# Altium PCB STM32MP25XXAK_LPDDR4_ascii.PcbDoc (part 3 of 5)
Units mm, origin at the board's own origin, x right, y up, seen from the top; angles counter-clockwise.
Board outline 120 x 79.6 mm, 4 copper layers (Top Layer, Signal Layer 1, Signal Layer 2, Bottom Layer), stack 1.614 mm thick; 190 components, 143 nets, 1208 pads, 757 vias.
Unrouted connection lines stored in the file: 3.
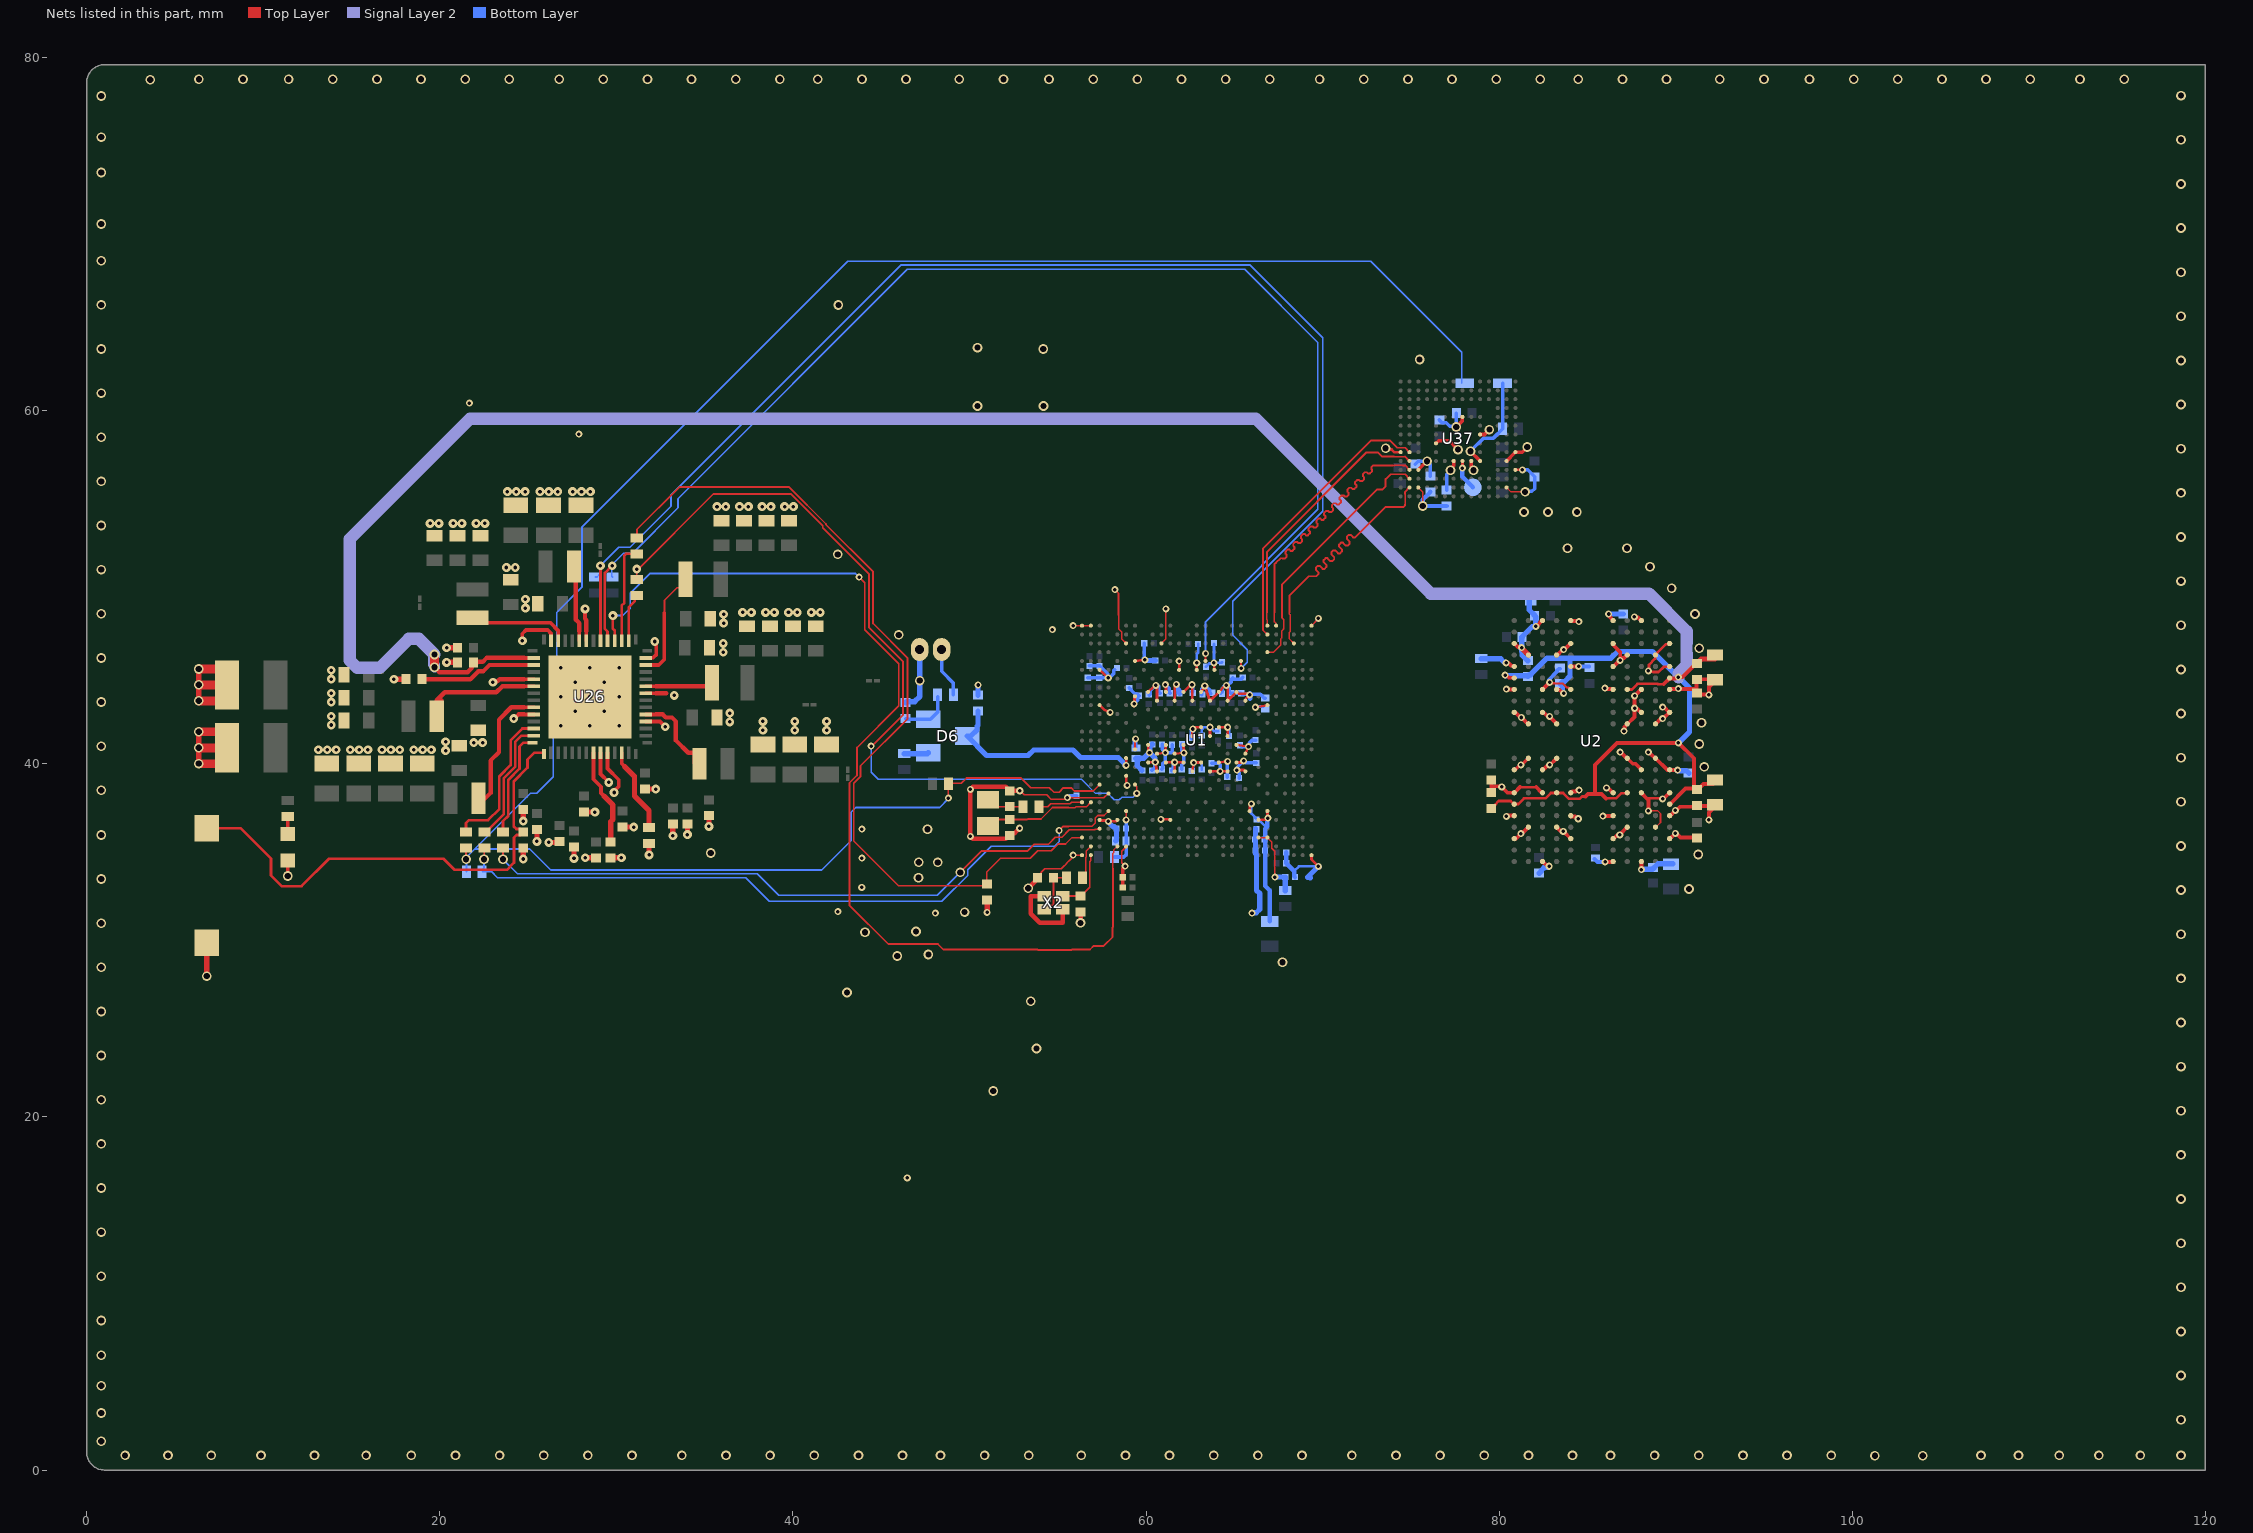
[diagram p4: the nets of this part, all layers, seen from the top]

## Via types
v1: diameter 0.55, hole 0.35, Top Layer to Bottom Layer, 277 vias
v2: diameter 0.4, hole 0.2, Top Layer to Bottom Layer, tented both sides, 229 vias
v3: diameter 0.5, hole 0.2, Top Layer to Bottom Layer, 146 vias
v4: diameter 0.4, hole 0.2, Top Layer to Bottom Layer, 105 vias

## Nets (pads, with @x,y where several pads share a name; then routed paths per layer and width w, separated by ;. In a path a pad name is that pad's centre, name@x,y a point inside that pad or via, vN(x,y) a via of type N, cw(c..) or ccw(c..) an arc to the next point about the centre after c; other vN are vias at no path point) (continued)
eMMC.SDMMC2_D3: U1.C25 U37.B2 | length 15.5
  Top Layer w0.09: 68.125,48.575 68.125,48.489 68.165,48.449 68.165,47.498 68.125,47.458 68.125,47.075 U1.C25@68.375,46.825 ; 74.675,54.705 74.675,55.273
  Top Layer w0.11: 68.125,48.575 68.125,49.525 69.225,50.625 69.647,50.625 69.723,50.702 69.762,50.741 69.762,50.85 69.621,50.991 69.621,51.101 69.731,51.211 69.84,51.211 70.004,51.046 70.114,51.046 70.224,51.156 70.224,51.266 70.059,51.43 70.059,51.539 70.169,51.649 70.279,51.649 70.443,51.485 70.552,51.485 70.662,51.594 70.662,51.704 70.498,51.868 70.498,51.978 70.607,52.087 70.717,52.087 70.881,51.923 70.991,51.923 71.1,52.033 71.1,52.142 70.936,52.307 70.936,52.416 71.046,52.526 71.155,52.526 71.32,52.362 71.429,52.362 71.539,52.471 71.539,52.581 71.375,52.745 71.375,52.855 71.484,52.964 71.594,52.964 71.735,52.823 71.845,52.823 71.887,52.865 73.582,54.56 74.596,54.56 74.675,54.639 74.675,54.705 ; 74.675,55.273 74.675,55.405 U37.B2@74.925,55.655
eMMC.SDMMC2_D4: U1.D22 U37.B3 | length 14.7
  Top Layer w0.09: U1.D22@66.902,46.352 U1.D22@66.875,46.325 67.229,46.325 67.625,46.721 67.625,47.075 67.7,47.15 67.7,47.541 67.805,47.647 67.805,48.17 67.7,48.275 ; 74.056,56.405 74.543,56.405
  Top Layer w0.11: 67.7,48.275 67.692,48.283 67.692,50.142 73.1,55.55 73.4,55.55 73.575,55.725 73.575,56.125 73.855,56.405 74.056,56.405 ; 74.543,56.405 74.675,56.405 U37.B3@74.925,56.155
eMMC.SDMMC2_D5: U1.A23 U37.B4 | length 17.3
  Top Layer w0.09: 67.267,48.575 67.267,48.055 67.349,47.973 67.349,47.851 U1.A23@67.375,47.825 ; 74.056,56.905 74.543,56.905
  Top Layer w0.11: 67.267,48.575 67.267,51.292 67.362,51.387 67.621,51.646 67.73,51.646 67.75,51.625 67.86,51.625 67.97,51.735 67.97,51.845 67.901,51.913 67.901,52.022 68.011,52.132 68.121,52.132 68.189,52.064 68.298,52.064 68.408,52.173 68.408,52.283 68.34,52.351 68.34,52.461 68.449,52.57 68.559,52.57 68.627,52.502 68.737,52.502 68.846,52.612 68.846,52.721 68.778,52.79 68.778,52.899 68.888,53.009 68.997,53.009 69.066,52.941 69.175,52.941 69.285,53.05 69.285,53.16 69.217,53.228 69.217,53.338 69.326,53.447 69.436,53.447 69.504,53.379 69.614,53.379 69.723,53.489 69.723,53.598 69.655,53.666 69.655,53.776 69.765,53.886 69.874,53.886 69.942,53.817 70.052,53.817 70.162,53.927 70.162,54.037 70.093,54.105 70.093,54.214 70.203,54.324 70.313,54.324 70.381,54.256 70.49,54.256 70.6,54.365 70.6,54.475 70.532,54.543 70.532,54.653 70.641,54.762 70.751,54.762 70.819,54.694 70.929,54.694 71.038,54.804 71.038,54.913 70.97,54.982 70.97,55.091 71.08,55.201 71.189,55.201 71.258,55.133 71.367,55.133 71.477,55.242 71.477,55.352 71.409,55.42 71.409,55.53 71.518,55.639 71.628,55.639 71.696,55.571 71.806,55.571 71.915,55.681 71.915,55.79 71.847,55.858 71.847,55.968 71.957,56.078 72.066,56.078 72.134,56.01 72.244,56.01 72.354,56.119 72.354,56.229 72.285,56.297 72.285,56.406 72.395,56.516 72.505,56.516 72.573,56.448 72.682,56.448 72.792,56.558 72.792,56.667 72.772,56.687 72.772,56.797 72.88,56.905 72.912,56.905 74.056,56.905 ; 74.543,56.905 74.675,56.905 U37.B4@74.925,56.655
eMMC.SDMMC2_D6: U1.A22 U37.B5 | length 14.8
  Top Layer w0.09: 66.847,48.356 66.847,48.176 66.875,48.148 U1.A22@66.875,47.825 ; 74.056,57.405 74.675,57.405
  Top Layer w0.096: 66.847,48.356 66.847,48.575
  Top Layer w0.11: 66.847,48.575 66.847,51.997 72.49,57.64 73.14,57.64 73.375,57.405 74.056,57.405 ; 74.675,57.405 U37.B5@74.925,57.155
eMMC.SDMMC2_D7: U1.B22 U37.B6 | length 16.1
  Top Layer w0.09: 66.625,48.575 66.625,47.575 U1.B22@66.875,47.325 ; 74.307,57.905 74.543,57.905
  Top Layer w0.11: 66.625,48.575 66.625,52.197 72.738,58.31 73.836,58.31 74.241,57.905 74.307,57.905 ; 74.543,57.905 74.675,57.905 U37.B6@74.925,57.655
GND: B2.1 C2.1 C3.1 C4.2 C5.2 C6.2 C7.2 C8.2 C9.1 C10.1 C11.1 C12.2 C13.2 C14.2 C15.2 C16.2 C17.2 C18.2 C19.2 C20.2 C21.2 C22.1 C23.1 C24.1 C26.1 C27.1 C28.1 C29.1 C30.1 C32.1 C33.1 C34.1 C35.1 C36.1 C37.1 C38.1 C39.1 C40.1 C41.1 C42.2 C43.1 C44.2 C45.1 C46.1 C47.2 C48.1 C49.1 C50.1 C51.1 C52.1 C53.1 C54.1 C55.1 C56.1 C57.1 C58.1 C59.1 C60.1 C61.1 C62.2 C63.1 C64.1 C65.2 C66.1 C67.1 C68.1 C69.1 C70.2 C71.1 C72.1 C73.2 C74.1 C75.1 C76.1 C77.2 C81.2 C82.1 C83.1 C86.2 C87.1 C88.1 C90.1 C91.2 C92.2 C117.1 C118.1 C128.1 C130.1 C147.2 C148.1 C151.1 C183.1 C184.1 C185.1 C186.1 C187.1 C188.1 C189.1 C190.2 C192.1 C193.1 C194.1 C195.1 C196.1 C197.1 C198.1 C199.1 C200.1 C201.1 C202.1 C203.1 C204.1 C205.1 C206.1 C207.1 C208.2 C209.1 C213.1 C214.2 C215.2 C216.1 C217.2 C219.1 C220.1 C225.1 C234.1 C235.1 C236.1 C237.1 C238.1 C239.1 C240.1 C244.1 C246.1 C248.1 C250.1 C251.1 C252.1 C253.1 C260.1 CN12.2 LD11.2 R1.1 R42.1 R57.1 U1.1A1 U1.1A3 U1.1A5 U1.1A7 U1.1A9 U1.1A11 U1.1B2 U1.1B4 U1.1B6 U1.1B8 U1.1B10 U1.1B12 U1.1E7 U1.1E9 U1.1F6 U1.1F8 U1.1F10 U1.1G1 U1.1G3 U1.1G5 U1.1G11 U1.1H2 U1.1H4 U1.1H12 U1.1J1 U1.1J3 U1.1J5 U1.1J7 U1.1J9 U1.1J11 U1.1K2 U1.1K4 U1.1K6 U1.1K8 U1.1K10 U1.1K12 U1.A1 U1.A2 U1.A27 U1.AC3 U1.AC5 U1.AC11 U1.AF6 U1.AG1 U1.AG27 U1.C6 U1.C10 U1.E7 U1.F3 U1.F12 U1.F14 U1.F16 U1.J7 U1.K3 U1.V6 U1.Y4 U2.A3 U2.A10 U2.AB3 U2.AB5 U2.AB8 U2.AB10 U2.C1 U2.C5 U2.C8 U2.C12 U2.D2 U2.D4 U2.D9 U2.D11 U2.E1 U2.E5 U2.E8 U2.E12 U2.G1 U2.G3 U2.G5 U2.G8 U2.G10 U2.G12 U2.J1 U2.J3 U2.J10 U2.J12 U2.K2 U2.K4 U2.K9 U2.K11 U2.N2 U2.N4 U2.N9 U2.N11 U2.P1 U2.P3 U2.P10 U2.P12 U2.T1 U2.T3 U2.T5 U2.T8 U2.T10 U2.T12 U2.V1 U2.V5 U2.V8 U2.V12 U2.W2 U2.W4 U2.W9 U2.W11 U2.Y1 U2.Y5 U2.Y8 U2.Y12 U26.9 U26.10 U26.18 U26.22 U26.27 U26.36 U26.41 U26.47 U26.52 U26.57 U37.A6 U37.C4 U37.E7 U37.G5 U37.H10 U37.J5 U37.K8 U37.N2 U37.N5 U37.P4 U37.P6 X2.2 X2.4 | length 235.9
  Top Layer w0.09: v2(55.55,38.085) 55.565,38.07 56.266,38.07 56.271,38.075 57.612,38.075 57.862,38.325 U1.Y4@57.875,38.325 ; U1.A1@56.375,47.825 U1.A2@56.875,47.825 ; 58.445,48.418 58.445,47.647 58.625,47.467 58.625,47.075 U1.C6@58.875,46.825 ; v2(58.816,34.213) 58.625,34.404 58.625,35.05 58.875,35.3 U1.AF6@58.875,35.325 ; U1.C10@60.875,46.825 61.125,47.075 v2(61.125,48.775) ; U37.N2@80.425,55.655 80.675,55.405 v1(81.475,55.405) ; U2.T10@82.459,44.194 U2.T10@82.459,44.207 ; v4@82.859,44.607 82.859,44.619 v4@82.937,44.619 ; v4@86.859,40.669 86.872,40.669 v4@86.884,40.669 ; U2.K4@87.234,40.319 U2.K4@87.259,40.319 ; v4@88.459,37.344 88.467,37.352 88.976,37.352 89.145,37.183 89.145,36.68 U2.D2@88.859,36.394
  Top Layer w0.1: v2(52.85,38.475) 52.882,38.475 53.114,38.244 54.372,38.244 54.622,37.994 55.458,37.994 v2(55.55,38.085) ; v1@53.243,33.041 v1(53.329,32.955) ; C92.2@53.859,33.546 53.859,33.648 54.264,34.053 55.189,34.053 55.279,34.144 55.291,34.144 55.496,34.349 55.496,34.361 55.77,34.635 55.77,34.639 55.875,34.744 v2(55.875,34.825) U1.AG1@56.375,34.825 ; v2(55.875,47.825) U1.A1@56.375,47.825 ; v2(58.24,49.865) 58.445,49.66 58.445,48.418 ; U1.A27@69.375,47.825 69.762,48.213 v2(69.762,48.238) ; v4(83.66,46.465) 83.685,46.465 v4@83.723,46.503 ; U2.Y8@84.035,46.815 U2.Y8@84.06,46.815 ; U2.V8@84.06,45.515 84.064,45.519 U2.V8@84.084,45.519 ; v4@84.505,45.519 v4(84.509,45.523)
  Top Layer w0.125: v4@82.974,44.57 83.12,44.57 83.144,44.545 83.616,44.545 83.835,44.326 83.9,44.326 84.018,44.208 U2.T8@84.018,44.194
  Top Layer w0.15: U1.AC3@57.375,36.825 57.41,36.79 57.795,36.79 57.845,36.74 v2(57.872,36.74) 58.29,36.74 U1.AC5@58.375,36.825 ; U1.K3@57.375,43.325 57.643,43.057 v2(57.966,42.92) ; U1.F3@57.375,45.325 v2(57.862,44.875) ; U1.V6@58.875,39.325 58.875,38.893 58.925,38.843 v2(58.925,38.775) ; v2@59.325,43.275 59.35,43.3 59.35,43.613 ; v2(59.325,43.4) 59.35,43.613 ; U1.E7@59.375,45.825 v2(59.931,45.892) ; U1.J7@59.388,43.812 U1.J7@59.375,43.825 ; U1.1J1@60.125,40.075 v2(60.525,40.1) U1.1K2@60.625,39.575 ; U1.1G1@60.125,41.075 60.125,40.778 60.198,40.705 v2(60.198,40.638) ; U1.1A1@60.125,44.075 60.442,44.392 60.481,44.392 60.531,44.442 v2@60.555,44.442 ; v2(60.558,44.442) v2@60.555,44.442 ; U1.1H2@60.625,40.575 v2(61.092,40.638) U1.1G3@61.125,41.075 ; U1.1B2@60.625,43.575 60.625,44.371 v2@60.555,44.442 ; v2(60.841,36.854) 61.289,36.854 61.303,36.84 61.36,36.84 U1.AC11@61.375,36.825 ; U1.1J3@61.125,40.075 v2(61.625,40.089) ; U1.1A3@61.125,44.075 61.132,44.082 v2@61.132,44.466 ; U1.1K4@61.625,39.575 v2(61.625,40.089) ; U1.1H4@61.625,40.575 v2(62.15,40.625) U1.1G5@62.125,41.075 ; U1.1B4@61.625,43.575 61.625,44.405 v2(61.725,44.505) ; U1.F12@61.875,45.325 v2(61.875,45.825) ; U1.1J5@62.125,40.075 v2(61.625,40.089) ; U1.1A5@62.125,44.075 62.496,44.446 62.571,44.446 62.625,44.5 U1.1B6@62.625,43.575 ; U1.1K6@62.625,39.575 v2(62.7,40.075) U1.1J7@63.125,40.075 ; U1.1F6@62.625,41.575 62.625,41.95 v2(62.65,41.975) ; v2@62.657,41.975 62.718,41.975 62.818,42.075 U1.1E7@63.125,42.075 ; U1.F14@62.875,45.325 v2(62.875,45.725) ; U1.1A7@63.125,44.075 v2(63.328,44.412) U1.1B8@63.625,43.575 U1.1A9@64.125,44.075 64.448,44.398 64.538,44.398 64.586,44.446 64.625,44.407 U1.1B10@64.625,43.575 U1.1A11@65.125,44.075 65.147,44.075 65.25,43.972 65.818,43.972 65.865,43.925 65.865,43.894 65.64,43.669 65.64,43.59 U1.1B12@65.625,43.575 ; U1.1K8@63.625,39.575 v2(64.198,39.575) U1.1K10@64.625,39.575 ; U1.1F8@63.625,41.575 v2(63.625,42.075) ; v2@63.853,45.725 U1.F16@63.875,45.325 ; U1.1E9@64.125,42.075 v2(64.625,42.075) U1.1F10@64.625,41.575 ; U1.1G11@65.125,41.075 v2(65.806,40.972) U1.1H12@65.625,40.575 ; U1.AG27@69.375,34.825 69.375,34.59 v2(69.768,34.197) ; v1(73.575,57.875) 73.646,57.804 73.911,57.804 74.056,57.66 74.42,57.66 U37.A6@74.425,57.655 ; U37.P4@80.925,56.655 v2(81.325,56.655) ; 81.193,38.681 81.527,38.681 81.531,38.684 81.791,38.684 81.795,38.681 82.106,38.681 ; v4@82.937,44.619 82.937,44.609 82.974,44.572 v4@82.974,44.57 ; U2.T8@84.018,44.194 U2.T8@84.059,44.194 ; 88.348,38.055 88.724,38.055 88.729,38.05 89.228,38.05 v4@89.259,38.019 ; U2.W2@88.859,46.169 88.859,46.196 89.433,46.77 89.562,46.77 U2.Y1@89.608,46.816 ; U2.W2@88.86,46.168 88.843,46.151 88.843,45.957 88.495,45.609 88.495,45.298 88.45,45.253 88.486,45.217 88.711,45.217 88.729,45.2 89.033,45.2 89.334,45.501 U2.V1@89.652,45.501 ; 59.35,43.613 59.35,43.825 U1.J7@59.375,43.825 ; 59.35,43.613 U1.J7@59.375,43.825
  Top Layer w0.16: U1.1J9@64.125,40.075 v2(64.625,40.143) ; U1.1J11@65.125,40.075 65.435,40.075 v2(65.53,40.17) ; v2(65.15,39.65) 65.55,39.65 U1.1K12@65.625,39.575
  Top Layer w0.2: v1@11.386,33.645 LD11.2@11.386,34.522 ; U26.27@31.67,46 32.079,46 32.27,46.191 32.27,46.91 v3@32.316,46.956 ; v3(32.17,46.93) v3@32.227,46.873 ; C248.1@58.683,33.002 C250.1@58.683,33.572 58.683,34.08 v2(58.816,34.213) ; U37.C4@75.425,56.655 75.875,57.105 75.885,57.105 v1(75.925,57.145) ; U37.E7@76.425,58.155 76.575,58.305 77.17,58.305 v1(77.675,57.8) ; v1(77.25,56.63) 77.25,56.718 77.425,56.893 U37.G5@77.425,57.155 ; v1(77.575,59.08) 77.925,59.43 U37.H10@77.925,59.655 ; U37.J5@78.425,57.155 78.425,56.85 78.55,56.725 v1(78.55,56.63) ; U37.K8@78.925,58.655 79.175,58.655 v1(79.45,58.93) ; U37.N5@80.425,57.155 U37.P6@80.925,57.655 81.305,57.655 v1(81.6,57.95) ; U2.J12@80.86,39.665 80.914,39.665 81.164,39.915 81.247,39.915 81.648,40.315 U2.K11@81.66,40.315
  Top Layer w0.21: v3(24.675,46.975) 24.675,47.375 24.88,47.58 26.109,47.58 26.3,47.389 U26.41@26.3,46.97 ; 24.775,42.8 U26.52@25.33,42.8 ; 24.775,44.8 U26.47@25.33,44.8 ; U26.36@28.3,46.97 28.3,47.525 ; U26.9@29.1,40.63 29.1,39.42 v3(29.568,38.952) ; U26.10@29.5,40.63 29.5,39.734 30.135,39.099 30.135,38.72 29.87,38.456 v3(29.87,38.377) ; U26.18@31.67,42.4 32.472,42.4 v3(32.772,42.1) ; U26.22@31.67,44 32.225,44
  Top Layer w0.22: C5.2@79.559,38.379 79.559,38.73 ; C13.2@79.559,39.08 79.559,38.73 ; v4@80.151,38.625 v4@80.2,38.625 ; v4(80.4,45.719) 80.527,45.719 80.693,45.554 80.765,45.554 80.788,45.53 80.85,45.53 U2.V12@80.86,45.521 ; v4@80.41,37.025 80.45,37.065 U2.E12@80.86,37.065 ; v4@80.425,44.215 U2.T12@80.86,44.215 ; U2.G12@80.83,38.38 U2.G12@80.845,38.365 ; U2.G12@80.854,38.356 U2.G12@80.845,38.365 ; U2.P12@80.859,42.894 80.874,42.879 80.949,42.879 81.149,42.679 81.17,42.679 81.293,42.556 81.293,42.535 81.347,42.535 81.637,42.244 U2.N11@81.659,42.244 ; U2.C12@80.86,35.765 80.875,35.78 80.975,35.78 v4(81.24,36.045) 81.288,36.045 U2.D11@81.658,36.415 ; U2.G12@80.86,38.365 U2.G12@80.845,38.365 ; U2.Y12@80.86,46.815 80.882,46.815 81.073,46.623 81.236,46.623 v4(81.271,46.589) ; U2.G12@80.87,38.36 81.19,38.681 81.193,38.681 ; v4(82.085,47.79) 82.113,47.79 82.438,48.115 U2.AB10@82.46,48.115 ; 82.106,38.681 82.378,38.409 82.399,38.409 82.452,38.356 U2.G10@82.456,38.356 ; U2.A10@82.459,34.444 82.465,34.45 82.496,34.45 82.716,34.229 82.799,34.229 v4@82.833,34.195 ; U2.J10@82.459,39.644 82.481,39.644 82.721,39.885 82.825,39.885 82.859,39.919 82.872,39.919 83.247,40.294 U2.K9@83.259,40.294 ; U2.P10@82.459,42.894 82.474,42.879 82.557,42.879 82.842,42.594 v4@82.897,42.594 ; U2.T10@82.459,44.207 v4@82.859,44.607 ; v4(82.86,42.69) 82.859,42.677 83.259,42.278 U2.N9@83.259,42.265 ; U2.W9@83.259,46.144 83.281,46.144 83.571,46.435 83.625,46.435 83.693,46.503 v4@83.723,46.503 ; U2.D9@83.26,36.415 83.5,36.175 v4(83.635,36.175) ; v4@83.641,36.175 U2.C8@84.059,35.756 ; v4@83.747,46.503 v4@83.723,46.503 ; U2.Y8@84.035,46.815 v4@83.723,46.503 ; U2.E8@84.059,37.044 84.074,37.029 84.301,37.029 84.435,36.894 v4@84.484,36.894 ; U2.G8@84.059,38.365 84.081,38.365 84.16,38.444 84.336,38.444 84.372,38.481 84.497,38.481 v4@84.534,38.444 ; U2.AB8@84.06,48.115 84.075,48.1 84.421,48.1 84.466,48.054 v4(84.515,48.054) ; U2.V8@84.072,45.507 U2.V8@84.084,45.519 ; U2.V8@84.088,45.523 U2.V8@84.084,45.519 ; v4@84.505,45.519 U2.V8@84.084,45.519 ; v4@85.885,37.04 85.891,37.046 86.384,37.046 86.388,37.05 86.445,37.05 U2.E5@86.46,37.065 ; v4(85.99,44.285) 86.039,44.285 86.093,44.23 86.445,44.23 U2.T5@86.46,44.215 ; v4(86.085,38.64) 86.118,38.606 86.197,38.606 U2.G5@86.446,38.356 ; v4(86.21,48.489) 86.244,48.455 86.244,48.352 86.46,48.137 U2.AB5@86.46,48.115 ; U2.C5@86.459,35.744 86.461,35.744 86.663,35.946 86.791,35.946 U2.D4@87.26,36.415 ; U2.V5@86.46,45.515 86.482,45.515 86.832,45.865 v4(86.86,45.865) v4@86.86,45.988 ; U2.Y5@86.46,46.815 86.475,46.8 86.475,46.716 86.86,46.331 v4@86.86,45.988 ; v4@86.8,35.946 v4(86.835,35.981) ; v4@86.872,40.669 87.247,40.294 U2.K4@87.259,40.294 ; v4(87.075,41.85) 87.109,41.884 87.109,42.093 U2.N4@87.26,42.243 ; U2.K4@87.259,40.315 87.57,40.004 87.72,40.004 U2.J3@88.059,39.665 ; U2.N4@87.26,42.265 U2.N4@87.26,42.243 ; U2.W4@87.26,46.165 87.083,45.988 v4@86.86,45.988 ; v4(87.661,48.325) 87.695,48.291 87.863,48.291 88.038,48.115 U2.AB3@88.06,48.115 ; v4@87.678,43.153 87.715,43.116 87.838,43.116 88.038,42.915 U2.P3@88.06,42.915 ; v4@88.059,33.994 U2.A3@88.059,34.444 ; U2.G3@88.059,38.344 88.348,38.055 88.459,37.944 v4@88.459,37.344 ; U2.T3@88.06,44.215 88.04,44.215 v4(87.675,43.85) v4(87.675,43.15) 87.675,42.658 U2.N4@87.26,42.243 ; v4@88.459,40.669 88.472,40.669 88.847,40.294 U2.K2@88.859,40.294 ; U2.N2@88.859,42.244 89.15,42.535 89.225,42.535 v4@89.259,42.569 ; U2.K2@88.86,40.315 89.531,39.644 89.659,39.644 v4@90.109,39.644 ; v4@89.259,38.019 89.293,38.053 89.347,38.053 89.637,38.344 U2.G1@89.659,38.344 ; v4@89.259,43.219 89.334,43.219 U2.P1@89.638,42.915 ; v4(89.26,42.565) 89.288,42.565 U2.P1@89.638,42.915 ; U2.C1@89.659,35.744 89.954,36.039 v4@89.954,36.147 ; U2.E1@89.659,37.044 89.672,37.044 89.972,37.344 90.033,37.344 90.258,37.569 C7.2@91.159,37.569 ; U2.P1@89.659,42.894 U2.P1@89.638,42.915 ; U2.T1@89.659,44.194 U2.T1@89.681,44.194 ; U2.T1@89.659,44.244 90.16,44.244 C14.2@91.184,44.244 ; U2.P1@89.66,42.915 U2.P1@89.638,42.915 ; v4@90.033,36.069 90.033,36.066 90.068,36.031 90.071,36.031 90.283,35.819 C15.2@91.159,35.819 ; C7.2@91.159,37.694 C7.2@91.247,37.607 ; C7.2@91.245,37.606 92.095,37.606 C3.1@92.183,37.519 ; C14.2@91.263,43.939 91.85,43.939 v4(91.884,43.905) 91.899,43.92 91.899,44.36 92.083,44.544 91.833,44.794 91.184,44.794 C14.2@91.184,44.244 ; C14.2@91.264,43.939 91.184,44.019 C14.2@91.184,44.244 ; v4(91.884,36.829) 91.899,36.845 91.899,37.255 92.138,37.494 92.233,37.494 C3.1@92.208,37.519 ; 79.559,38.73 80.121,38.73 v4(80.15,38.7) 80.485,38.365 U2.G12@80.845,38.365
  Top Layer w0.25: v3(23.008,44.625) 23.056,44.673 23.257,44.673 23.384,44.8 24.775,44.8 ; v3(24.187,42.563) 24.221,42.563 24.459,42.8 24.775,42.8 ; v3(28.225,48.775) 28.225,48.214 28.3,48.139 28.3,47.525 ; 32.225,44 32.83,44 ; v3@32.757,42.1 v3(32.772,42.1) ; v2(52.841,36.352) 52.569,36.08 52.415,36.08 C86.2@52.285,35.95 52.26,35.95 52.061,35.75 50.196,35.75 v2(50.05,35.897) v2(50.05,38.554) 50.196,38.7 52.06,38.7 C81.2@52.285,38.475 v2(52.85,38.475) ; v1(53.329,32.955) 53.729,33.355 53.729,33.416 C92.2@53.859,33.546 ; X2.2@54.234,32.51 53.467,32.51 53.467,31.513 53.987,30.993 55.284,30.993 X2.4@55.284,31.76 ; v1(56.293,30.993) C90.1@56.293,31.61
  Top Layer w0.3: v1@6.347,40.012 v1@6.347,41.812 ; v1@6.347,43.574 v1@6.347,45.374 ; B2.1@6.795,29.854 6.795,27.98 v1(6.8,27.975) ; v3(17.395,44.79) C43.1@18.055,44.79 ; v3(20.385,45.75) C40.1@20.995,45.75 ; v3(20.385,46.575) C39.1@20.995,46.575 ; v3@24.725,36.81 C217.2@24.725,37.42 ; v3@24.727,34.58 C219.1@24.727,35.185 ; v3(25.5,35.61) C216.1@25.5,36.215 ; v3(26.165,35.55) C215.2@26.775,35.55 ; v3@27.6,34.69 C214.2@27.6,35.3 ; C213.1@28.175,37.27 v3(28.785,37.27) ; v3(28.24,34.68) C91.2@28.85,34.68 ; C208.2@29.675,34.68 v3(30.285,34.68) ; C209.1@30.35,36.42 v3(30.985,36.42) ; C61.1@31.625,38.57 v3(32.235,38.57) ; v3(31.85,34.84) R57.1@31.85,35.5 ; v3(33.2,35.93) C189.1@33.2,36.59 ; v3(34.025,35.99) C188.1@34.025,36.59 C188.1@34.025,36.65 ; v3(35.245,36.46) 35.248,36.462 35.248,37.062 C190.2@35.25,37.065 ; v2@50.979,31.565 v2(51,31.586) C33.1@51,32.3 ; v4(80.41,44.23) v4@80.425,44.215 ; v4(81.271,46.589) 81.271,46.562 81.66,46.173 U2.W11@81.66,46.165
  Top Layer w0.5: v1@6.353,40.006 C147.2@7.936,40.006 ; v1@6.353,40.906 C147.2@7.936,40.906 ; v1@6.353,41.818 C147.2@7.936,41.818 ; v1@6.353,43.568 C42.2@7.936,43.568 ; v1@6.353,44.468 C42.2@7.936,44.468 ; v1@6.353,45.38 C42.2@7.936,45.38
  Bottom Layer w0.1: C8.2@83.459,45.39 83.459,45.438 C8.2@83.461,45.44
  Bottom Layer w0.15: v2(59.931,45.892) v2@59.935,45.896 ; C57.1@62.592,39.603 62.683,39.694 62.683,40.058 v2(62.7,40.075) 63.066,40.075 63.154,39.987 C60.1@63.154,39.672 ; v2(62.875,45.725) 62.875,46.219 62.95,46.294 C195.1@62.95,46.787 ; C52.1@63.162,41.607 63.162,41.944 63.293,42.075 v2(63.625,42.075) 63.844,41.856 C53.1@64.083,41.856 ; C67.1@63.4,45.5 63.586,45.686 63.807,45.686 v2@63.859,45.738 ; v2(63.85,45.725) 64.278,45.725 C69.1@64.305,45.752 ; v2@63.85,45.775 C239.1@63.85,46.787 ; v2(64.625,42.075) 64.706,41.994 C54.1@64.706,41.579 ; 68.39,33.919 68.669,34.197 v2(69.768,34.197)
  Bottom Layer w0.2: v2(55.55,38.085) 55.663,38.198 C234.1@56.064,38.198 ; C237.1@56.696,44.88 C236.1@57.345,44.88 ; C192.1@56.8,45.55 C201.1@57.375,45.55 57.825,45.1 57.825,44.912 v2(57.862,44.875) 57.862,44.894 57.881,44.914 57.974,44.914 58.163,45.103 58.163,45.282 C197.1@58.216,45.334 ; C236.1@57.35,44.875 v2(57.862,44.875) ; C240.1@59.05,44.3 59.37,43.98 59.484,43.98 59.534,43.93 C220.1@59.534,43.856 ; v2(59.325,43.4) 59.325,43.408 59.534,43.617 59.534,43.781 C220.1@59.609,43.856 C220.1@59.534,43.931 ; v2@59.902,45.948 C205.1@59.902,46.829 ; C45.1@60.173,43.895 60.235,43.957 60.235,44.124 60.248,44.137 60.248,44.139 60.551,44.442 v2(60.558,44.442) ; C71.1@60.34,39.635 60.491,39.786 60.491,40.066 v2(60.525,40.1) ; v2@60.624,44.485 60.726,44.383 60.726,44.075 C51.1@60.813,43.988 ; C72.1@60.905,39.698 60.956,39.749 60.956,40.021 61.092,40.157 v2(61.092,40.638) ; C46.1@60.915,41.105 60.915,40.815 v2(61.092,40.638) ; v2@61.132,44.466 61.132,44.444 61.302,44.274 61.302,44.062 C49.1@61.377,43.987 ; C73.2@61.467,39.624 61.542,39.699 61.542,39.952 61.625,40.035 v2(61.625,40.089) ; C47.2@61.476,41.081 61.476,40.694 61.42,40.638 v2(61.092,40.638) ; C74.1@62.03,39.683 62.03,39.955 62.15,40.075 v2(62.15,40.625) 62.038,40.737 C48.1@62.038,41.107 ; C63.1@62.581,44.08 62.636,44.08 62.636,44.483 v2@62.625,44.494 ; C62.2@63.156,43.924 63.156,44.24 v2(63.328,44.412) 63.366,44.374 63.421,44.374 63.6,44.195 63.6,44.059 C65.2@63.675,43.984 ; C59.1@63.714,40.036 64.111,40.036 64.198,39.949 v2(64.198,39.575) ; C68.1@64.239,43.997 64.314,44.072 64.314,44.284 64.437,44.408 64.548,44.408 v2@64.586,44.446 ; C58.1@64.607,39.247 64.607,40.125 v2(64.625,40.143) ; C66.1@64.915,44.871 C66.1@64.84,44.796 ; C76.1@65.274,39.198 65.274,39.526 v2(65.15,39.65) 65.169,39.669 65.169,39.809 v2(65.53,40.17) 65.557,40.17 65.677,40.05 C77.2@66.25,40.05 ; C82.1@65.352,41.053 65.433,40.972 v2(65.806,40.972) 65.844,41.01 65.844,41.178 66.016,41.35 C75.1@66.205,41.35 ; C238.1@65.483,44.894 65.385,44.796 64.915,44.796 C66.1@64.84,44.796 ; R1.1@66.751,43.72 66.701,43.72 66.601,43.82 66.601,43.828 66.484,43.946 65.886,43.946 65.865,43.925 65.851,43.939 65.436,43.939 65.375,44 C64.1@64.85,44 64.804,44 64.8,43.996 64.725,44.071 64.725,44.307 v2@64.586,44.446 ; C118.1@75.26,56.98 75.425,57.145 v1(75.925,57.145) 76.11,56.96 C148.1@76.11,56.305 ; C9.1@76.615,59.48 76.77,59.325 77.008,59.325 77.208,59.126 77.529,59.126 v1(77.575,59.08) C117.1@77.575,59.864 ; C130.1@77.027,55.505 77.027,56.407 v1(77.25,56.63) ; v2(81.325,56.655) 81.615,56.655 C128.1@82.015,56.255 82.015,55.592 81.858,55.435 81.505,55.435 v1(81.475,55.405) ; v2@64.586,44.446 64.623,44.446 64.84,44.663 C66.1@64.84,44.796
  Bottom Layer w0.22: v4@82.825,44.749 82.814,44.76 83.291,45.236 83.291,45.295 83.386,45.39 C8.2@83.459,45.39 ; v4(82.86,44.615) 82.893,44.649 v4@82.893,44.777 ; v4(84.509,45.523) 84.511,45.525 C21.2@85.109,45.525
  Bottom Layer w0.25: C253.1@67.941,34.367 68.39,33.919 68.39,33.638 C251.1@68.44,33.588 ; C253.1@67.941,34.385 C246.1@67.941,34.986
  Bottom Layer w0.3: C88.1@46.382,43.465 46.439,43.522 46.897,43.522 47.189,43.814 CN12.2@47.189,46.897 ; C87.1@50.485,43.888 v2(50.485,44.466) ; v2(57.872,36.74) 57.891,36.721 57.891,36.682 58.133,36.44 58.216,36.44 C244.1@58.325,36.331 58.325,35.675 C235.1@58.275,35.625 ; C70.2@59.775,39.625 59.506,39.894 59.506,40.25 59.456,40.3 C225.1@59.425,40.3 59.451,40.326 59.886,40.326 v2(60.198,40.638) ; v2@59.902,45.948 59.931,45.919 v2(59.931,45.892) 59.958,45.892 60,45.85 C196.1@60.525,45.85 ; C44.2@60.351,41.105 60.217,40.971 60.217,40.657 v2(60.198,40.638) ; v2(60.525,40.1) 60.506,40.119 60.506,40.33 v2(60.198,40.638) ; v2(61.725,44.505) 61.725,44.478 61.75,44.453 61.75,44.284 61.875,44.159 61.875,44.025 C50.1@61.9,44 ; C55.1@62.6,41.475 62.604,41.479 62.604,41.901 62.65,41.948 v2(62.65,41.975) ; v2@65.889,43.718 v2@65.889,43.969 ; v2@65.984,31.527 v2(66.003,31.546) 66.023,31.565 66.243,31.565 66.449,31.771 66.449,32.645 66.258,32.836 66.258,34.855 66.2,34.914 C252.1@66.2,36.324 ; 69.301,33.541 69.259,33.583 69.16,33.583 69.75,34.173 69.769,34.192 69.788,34.173 v2@69.829,34.173 ; v1(75.5,62.9) v1@75.51,62.91 ; R42.1@78.986,45.955 80.087,45.955 80.287,45.754 v4@80.314,45.754 ; v4@81.241,46.521 81.279,46.559 C12.2@81.279,47.149 ; 81.28,46.368 81.299,46.349 81.299,46.152 81.604,45.847 C4.2@81.63,45.847 ; C12.2@81.311,47.18 C12.2@81.279,47.149 ; C10.1@81.786,49.415 81.709,49.338 81.709,48.715 82.025,48.399 C16.2@82.025,48.374 ; C16.2@81.984,48.415 C16.2@82.025,48.374 ; v4(82.085,47.79) 82.084,48.315 C16.2@82.025,48.374 ; v4@82.086,47.784 82.067,47.765 81.871,47.765 81.279,47.174 C12.2@81.279,47.149 ; C19.2@82.26,33.805 82.285,33.805 82.39,33.91 82.39,33.962 82.566,34.138 82.741,34.138 82.798,34.195 v4@82.833,34.195 ; v4@86.211,48.484 86.214,48.487 87.032,48.487 C17.2@87.036,48.49 ; v4@88.059,33.99 88.093,34.024 88.668,34.024 88.734,34.09 88.759,34.09 89.009,34.34 C11.1@89.834,34.34 ; v4@90.06,39.64 90.109,39.64 90.143,39.606 90.618,39.606 C20.2@90.759,39.465
  other v1: 101.286,0.805 104,0.805 2.175,0.83 4.6,0.83 7.05,0.83 9.875,0.83 12.9,0.83 15.825,0.83 18.386,0.83 20.886,0.83 23.386,0.83 25.886,0.83 28.386,0.83 30.886,0.83 33.711,0.83 36.211,0.83 38.711,0.83 41.211,0.83 43.711,0.83 46.211,0.83 48.361,0.83 50.861,0.83 53.361,0.83 56.336,0.83 58.836,0.83 61.336,0.83 63.836,0.83 66.336,0.83 68.836,0.83 71.661,0.83 74.161,0.83 76.661,0.83 79.161,0.83 81.661,0.83 84.161,0.83 86.311,0.83 88.811,0.83 91.311,0.83 93.811,0.83 96.311,0.83 98.811,0.83 107.3,0.83 109.425,0.83 111.725,0.83 113.975,0.83 116.325,0.83 118.625,0.83 0.825,1.625 118.625,2.85 0.825,3.225 0.825,4.775 118.625,5.35 0.825,6.5 118.625,7.85 0.825,8.475 118.625,10.35 0.825,10.975 118.625,12.85 0.825,13.475 118.625,15.35 0.825,15.975 118.625,17.85 0.825,18.475 118.625,20.35 0.825,20.975 51.35,21.475 118.625,22.85 0.825,23.475 53.8,23.875 118.625,25.35 0.825,25.975 53.467,26.55 43.063,27.05 118.625,27.85 0.825,28.475 67.73,28.759 45.909,29.117 47.672,29.202 118.625,30.35 44.087,30.462 46.975,30.5 0.825,30.975 49.725,31.6 118.625,32.85 90.755,32.906 0.825,33.475 47.112,33.546 11.387,33.648 47.125,34.425 48.2,34.42 91.285,34.865 35.35,34.945 118.625,35.35 0.825,35.975 47.625,36.3 118.625,37.85 0.825,38.5 91.617,39.829 6.348,40.014 118.625,40.35 6.348,40.914 0.825,41 91.339,41.128 6.348,41.814 91.467,42.332 118.625,42.85 0.825,43.5 6.348,43.576 6.348,44.476 47.189,44.713 118.625,45.35 6.348,45.376 0.825,46 91.339,46.544 45.995,47.305 118.625,47.85 0.825,48.5 91.101,48.492 89.772,49.948 118.625,50.35 0.825,51 88.551,51.167 42.535,51.865 83.87,52.208 87.25,52.216 118.625,52.85 0.825,53.5 81.406,54.265 82.774,54.265 84.406,54.265 118.625,55.35 0.825,56 118.625,57.85 0.825,58.5 50.45,60.275 54.195,60.275 118.625,60.35 0.825,61 118.625,62.85 0.825,63.5 54.175,63.5 50.45,63.575 118.625,65.35 0.825,66 42.575,65.995 118.625,67.85 0.825,68.5 118.625,70.35 0.825,70.575 118.625,72.85 0.825,73.5 118.625,75.35 0.825,75.5 0.825,77.825 118.625,77.85 3.6,78.75 6.35,78.775 8.85,78.775 11.436,78.775 13.936,78.775 16.436,78.775 18.936,78.775 21.436,78.775 23.936,78.775 26.761,78.775 29.261,78.775 31.761,78.775 34.261,78.775 36.761,78.775 39.261,78.775 41.411,78.775 43.911,78.775 46.411,78.775 49.425,78.775 51.925,78.775 54.511,78.775 57.011,78.775 59.511,78.775 62.011,78.775 64.511,78.775 67.011,78.775 69.836,78.775 72.336,78.775 74.836,78.775 77.336,78.775 79.836,78.775 82.336,78.775 84.486,78.775 86.986,78.775 89.486,78.775 92.5,78.775 95,78.775 97.586,78.775 100.086,78.775 102.586,78.775 105.086,78.775 107.586,78.775 110.086,78.775 112.911,78.775 115.411,78.775
  other v2: 46.475,16.55 48.075,31.55 42.551,31.633 43.9,33 43.902,34.655 43.902,36.305 65.87,43.91 64.55,44.448 61.1,44.49 62.606,44.48 54.694,47.6 27.875,58.675 21.675,60.437
  other v3: 24.722,34.61 27.6,34.64 24.725,36.76 20.325,40.75 13.124,40.798 13.625,40.798 14.126,40.798 14.924,40.798 15.425,40.798 15.926,40.798 16.724,40.798 17.225,40.798 17.726,40.798 18.524,40.798 19.025,40.798 19.526,40.798 21.924,41.202 22.425,41.202 20.325,41.25 38.304,41.9 40.104,41.9 41.904,41.9 26.85,42.15 28.5,42.15 30.15,42.15 13.85,42.2 36.42,42.375 38.304,42.401 40.104,42.401 41.904,42.401 13.85,42.7 36.42,42.875 27.675,42.975 29.325,42.975 13.85,43.5 26.85,43.8 28.5,43.8 30.15,43.8 33.28,43.875 13.85,44 27.675,44.625 29.325,44.625 13.85,44.8 13.85,45.3 26.85,45.45 28.5,45.45 30.15,45.45 36.05,46.325 36.05,46.825 36.075,47.975 36.075,48.475 37.15,48.575 37.65,48.575 38.45,48.575 38.95,48.575 39.75,48.575 40.25,48.575 41.05,48.575 41.55,48.575 24.85,48.823 24.85,49.323 23.775,51.123 24.276,51.123 19.45,53.623 19.951,53.623 20.75,53.623 21.251,53.623 22.05,53.623 22.551,53.623 35.7,54.575 36.2,54.575 36.975,54.575 37.475,54.575 38.25,54.575 38.75,54.575 39.525,54.575 40.025,54.575 23.824,55.425 24.325,55.425 24.826,55.425 25.674,55.425 26.175,55.425 26.676,55.425 27.524,55.425 28.025,55.425 28.526,55.425
  other v4: 88.06,34.015 82.83,34.2 89.985,36.065 84.485,36.89 80.41,37.02 85.885,37.04 88.46,37.34 89.985,37.365 89.26,38.015 84.535,38.515 90.11,39.64 82.86,39.94 81.235,39.945 86.86,40.665 88.46,40.665 81.26,42.625 89.26,43.215 90.16,44.265 88.46,45.265
HSE_IN: C90.2 U1.AG2 X2.1 | length 3.6
  Top Layer w0.1: X2.1@55.284,32.51 56.318,32.51 56.814,33.005 56.814,34.464 56.875,34.525 U1.AG2@56.875,34.825
HSE_OUT: R75.2 U1.AF2 | length 2
  Top Layer w0.09: 56.59,34.075 56.59,34.686 56.625,34.721 56.625,35.075 U1.AF2@56.875,35.325
  Top Layer w0.1: R75.2@56.409,33.546 56.59,33.727 56.59,34.075
I2C7.SCL: R261.1 U1.E15 U26.33 | length 74.8
  Top Layer w0.1: U1.E15@63.375,45.825 v2(63.375,46.25)
  Top Layer w0.15: U26.33@29.5,46.97 29.5,47.5 29.35,47.65 29.35,50.812 v3(29.763,51.225)
  Bottom Layer w0.1: R261.1@29.785,50.583 29.743,50.626 29.743,51.265 30.406,51.929 30.917,51.929 33.493,54.505 33.493,55.016 46.487,68.01 65.588,68.01 69.733,63.865 69.733,54.412 63.375,48.054 v2(63.375,46.25)
I2C7.SDA: R260.1 U1.E19 U26.34 | length 76.8
  Top Layer w0.125: U1.E19@65.375,45.825 65.375,45.44 v2@65.39,45.425
  Top Layer w0.15: U26.34@29.1,46.97 v3(29.1,51.225)
  Bottom Layer w0.1: R260.1@28.81,50.583 28.9,50.583 29.08,50.763 v3@29.08,51.228 ; v3@29.093,51.228 30.141,52.275 30.771,52.275 33.099,54.603 33.099,55.234 46.115,68.25 65.899,68.25 70.009,64.14 70.009,54.304 64.91,49.206 64.91,47.299 65.74,46.469 65.74,45.76 v2(65.39,45.41)
MP257_WAKEUP: U1.AF5 U26.32 | length 59.2
  Top Layer w0.09: 58.125,34.075 58.125,34.929 58.165,34.969 58.165,35.115 U1.AF5@58.375,35.325
  Top Layer w0.1: v2(43.751,50.58) 44.063,50.269 44.063,47.604 45.995,45.672 45.995,43.285 43.631,40.921 43.631,39.348 43.2,38.916 43.2,31.993 45.395,29.797 48.212,29.797 48.525,29.485 53.864,29.485 53.889,29.46 55.786,29.46 55.811,29.485 56.828,29.485 57.032,29.69 57.602,29.69 58.106,30.195 58.106,30.747 58.125,30.765 58.125,34.075
  Top Layer w0.15: v3(29.8,48.4) 29.8,47.653 29.9,47.553 U26.32@29.9,46.97
  Bottom Layer w0.1: v3@29.78,48.403 30.361,48.403 30.78,48.823 30.78,49.661 31.898,50.778 43.543,50.778 43.74,50.58 v2(43.751,50.58)
NetB2_2: B2.2 C219.2 U26.1 | length 28.3
  Top Layer w0.15: B2.2@6.795,36.354 8.721,36.354 10.438,34.637 10.438,33.673 11.036,33.075 12.162,33.075 13.713,34.625 20.219,34.625 20.845,33.999 23.799,33.999 24.2,34.4 24.2,35.825 24.347,35.972 24.554,35.972 C219.2@24.727,36.145 24.562,36.31 24.338,36.31 24.187,36.46 24.187,39.008 24.962,39.783 24.962,40.237 25.355,40.63 U26.1@25.9,40.63
NetC43_2: C43.2 U26.45 | length 6.7
  Top Layer w0.21: 24.775,45.6 U26.45@25.33,45.6
  Top Layer w0.25: C43.2@19.015,44.79 21.731,44.79 22.176,45.235 22.451,45.235 22.816,45.6 24.775,45.6
NetC81_1: C81.1 R64.2 X1.1 | length 2.1
  Top Layer w0.1: X1.1@51.059,37.975 51.459,37.575 C81.1@52.285,37.575 R64.2@53.035,37.575
NetC88_2: C88.2 D6.2 R66.2 | length 2.9
  Bottom Layer w0.2: C88.2@46.382,42.565 46.424,42.523 D6.2@47.673,42.523 47.792,42.523 48.192,42.923 R66.2@48.192,43.796
NetC92_1: C92.1 R75.1 X2.3 | length 2.9
  Top Layer w0.1: X2.3@54.234,31.76 54.461,31.987 54.694,31.987 54.759,32.052 C92.1@54.759,33.546 R75.1@55.509,33.546
NetC130_2: C130.2 C148.2 U37.C2 | length 3.5
  Top Layer w0.09: U37.C2@75.425,55.655 75.675,55.405 v1(75.675,54.605)
  Bottom Layer w0.25: C148.2@76.11,55.405 75.675,54.97 v1(75.675,54.605) C130.2@77.027,54.605
NetC151_2: C151.2 C252.2 C260.2 R11.2 U1.AB20 U1.AB22 U1.AC21 | length 9.2
  Top Layer w0.15: U1.AB20@65.875,37.325 65.875,37.607 65.95,37.682 v2@65.95,37.75 ; U1.AC21@66.375,36.825 66.8,36.825 v2@66.888,36.913
  Top Layer w0.16: U1.AB22@66.875,37.325 66.875,36.95 v2(66.9,36.925)
  Bottom Layer w0.15: v2(65.969,37.735) 65.95,37.716 65.95,37.205 66.167,36.988 66.167,36.95 66.367,36.75 66.466,36.75 66.821,36.395
  Bottom Layer w0.25: v2(66.9,36.925) 66.875,36.9 66.875,36.449 66.821,36.395 66.75,36.324 66.75,35.714 66.75,33.083 67,32.833 R11.2@67,31.075
NetC208_1: C208.1 U26.8 | length 5.4
  Top Layer w0.21: U26.8@28.7,40.63 28.7,39.134 29.125,38.709 29.125,38.345 29.298,38.172
  Top Layer w0.3: 29.298,38.172 29.8,37.67 29.8,36.843 29.675,36.718 C208.1@29.675,35.705
NetC225_2: C225.2 U1.R7 | length 1.1
  Top Layer w0.1: U1.R7@59.375,40.825 v2@59.375,41.41
  Bottom Layer w0.1: C225.2@59.375,40.95 C225.2@59.425,40.9
  Bottom Layer w0.3: C225.2@59.375,40.95 v2@59.375,41.41
  other v2: 59.41,41.41
NetC235_2: C235.2 C244.2 R267.1 U1.AB6 | length 3.2
  Top Layer w0.09: v2(58.875,36.825) U1.AB6@58.875,37.325
  Bottom Layer w0.2: R267.1@58.223,34.723 58.734,34.723 58.875,34.864 C235.2@58.875,35.625 C244.2@58.875,36.331 v2(58.875,36.825)
NetC251_2: C251.2 R286.2 U1.AE21 U1.AE22 | length 4.3
  Top Layer w0.09: U1.AE21@66.375,35.825 U1.AE22@66.875,35.825 ; U1.AE22@66.902,35.798 67.125,35.575 67.125,35.221 67.295,35.052 67.295,33.593 v2(67.3,33.588)
  Top Layer w0.1: U1.AE22@66.875,35.825 U1.AE22@66.902,35.798
  Bottom Layer w0.3: v2(67.3,33.588) C251.2@67.89,33.588 R286.2@67.89,32.815
NetCN12_1: CN12.1 R66.1 | length 3.2
  Bottom Layer w0.2: CN12.1@48.425,46.801 48.425,45.241 49.083,44.583 R66.1@49.083,43.917
NetD6_1: D6.1 R67.1 | length 1.4
  Bottom Layer w0.3: R67.1@46.3,40.575 47.625,40.575 D6.1@47.673,40.623
NetD7_1: D7.1 R248.1 U37.K5 | length 5.7
  Top Layer w0.2: v1(78.375,57.705) U37.K5@78.925,57.155
  Bottom Layer w0.2: v1(78.375,57.705) 79.125,58.455 79.682,58.455 R248.1@80.207,58.98 80.207,61.55 D7.1@80.195,61.563
NetL1_1: L1.1 U26.37 | length 4.2
  Top Layer w0.21: U26.37@27.9,46.97 27.9,47.525
  Top Layer w0.25: L1.1@27.7,51.135 27.7,48.173 27.9,47.973 27.9,47.525
NetL2_1: L2.1 U26.26 | length 6
  Top Layer w0.09: 32.725,48.56 32.725,49.26 33.433,49.968 33.56,49.968 33.915,50.323 L2.1@33.915,50.45
  Top Layer w0.2: U26.26@31.917,45.6 32.4,45.6 32.725,45.925 32.725,48.56
NetL3_1: L3.1 U26.40 | length 5.9
  Top Layer w0.15: L3.1@21.698,48.162 L3.1@21.85,48.01
  Top Layer w0.21: L3.1@21.85,48.275 22.135,47.99 23.91,47.99 26.265,47.99 26.7,47.555 U26.40@26.7,46.97
NetL4_1: L4.1 U26.23 | length 3.8
  Top Layer w0.15: L4.1@35.36,43.885 L4.1@35.36,44.4
  Top Layer w0.21: U26.23@31.67,44.4 32.225,44.4
  Top Layer w0.25: 32.225,44.4 35,44.4
NetL5_1: L5.1 U26.48 | length 7.2
  Top Layer w0.15: L5.1@19.618,42.448 L5.1@19.87,42.7 ; L5.1@20.09,42.585 L5.1@20.09,43.1
  Top Layer w0.21: 24.775,44.4 U26.48@25.33,44.4
  Top Layer w0.25: 19.825,43.6 20.275,44.05 23.2,44.05 23.55,44.4 24.775,44.4 ; L5.1@20.09,43.1 20.09,43.615
NetL6_1: L6.1 U26.19 | length 4.9
  Top Layer w0.21: U26.19@31.67,42.8 32.225,42.8
  Top Layer w0.25: 32.225,42.8 32.623,42.8 32.798,42.625 33.15,42.625 33.375,42.4 33.375,41.325 34.071,40.629 34.425,40.629 34.43,40.624 L6.1@34.43,40.025
NetL7_1: L7.1 U26.51 | length 7.4
  Top Layer w0.21: 24.775,43.2 U26.51@25.33,43.2
  Top Layer w0.25: L7.1@22.425,38.425 L7.1@22.425,38.669 ; L7.1@22.475,37.95 22.875,38.35 22.875,40.184 23.35,40.659 23.35,42.503 24.047,43.2 24.775,43.2
NetLD11_1: LD11.1 R210.2 | length 1
  Top Layer w0.2: LD11.1@11.386,36.022 R210.2@11.386,37.015
NetR1_2: R1.2 U1.K22 | length 1.6
  Top Layer w0.15: v2@66.201,43.202 U1.K22@66.875,43.325
  Bottom Layer w0.1: v2@66.201,43.2 66.671,43.2 R1.2@66.6,43.2
  Bottom Layer w0.15: v2@66.201,43.202 66.246,43.247 R1.2@66.6,43.247
  other v2: 66.2,43.205
NetR2_1: R2.1 U2.A5 | length 1.1
  Top Layer w0.22: v4@86.009,34.444 U2.A5@86.459,34.444
  Bottom Layer w0.22: R2.1@85.409,34.615 85.584,34.44 v4@86.009,34.44
  other v4: 86.01,34.45
NetR46_2: R46.2 U26.30 | length 2.8
  Top Layer w0.15: U26.30@30.7,46.97 30.7,48.87 31.032,49.202 31.032,49.43 R46.2@31.15,49.548
NetR57_2: R57.2 U26.12 | length 4.9
  Top Layer w0.21: U26.12@30.3,40.63 30.3,40.016 30.47,39.845
  Top Layer w0.3: 30.47,39.845 31.025,39.291 31.025,38.174 31.85,37.349 R57.2@31.85,36.4
NetR59_2: R59.2 U26.54 | length 8.5
  Top Layer w0.15: R59.2@21.48,36.145 21.48,36.64 21.65,36.81 22.736,36.81 23.375,37.449 23.375,39.298 24.012,39.935 24.012,41.335 24.677,42 U26.54@25.33,42
NetR60_2: R60.2 U26.55 | length 7.1
  Top Layer w0.15: R60.2@22.53,36.145 22.604,36.145 23.625,37.166 23.625,39.194 24.262,39.832 24.262,41.232 24.631,41.6 U26.55@25.33,41.6
NetR61_2: R61.2 U26.56 | length 6.1
  Top Layer w0.15: R61.2@23.58,36.145 23.58,36.76 23.875,37.055 23.875,39.091 24.512,39.728 24.512,40.985 24.727,41.2 U26.56@25.255,41.2
NetR81_2: R81.2 U26.31 | length 5.7
  Top Layer w0.15: U26.31@30.3,46.97 30.3,48.973 30.45,49.123 30.45,51.81 30.538,51.898 R81.2@31.163,51.898
NetTP21_1: TP21.1 U37.H5 | length 1.7
  Top Layer w0.15: v2(77.925,56.755) U37.H5@77.925,57.155
  Bottom Layer w0.25: v2(77.925,56.755) 77.925,56.256 TP21.1@78.516,55.665
NRST: C33.2 R81.1 U1.AE1 | length 49.7
  Top Layer w0.09: 55.444,35.457 55.812,35.825 U1.AE1@56.375,35.825
  Top Layer w0.1: R81.1@31.163,52.798 31.163,53.273 33.565,55.675 39.786,55.675 41.873,53.588 41.873,53.551 44.541,50.883 44.541,47.949 46.497,45.992 46.497,42.556 43.821,39.879 43.821,39.269 43.443,38.89 43.443,35.633 45.978,33.097 50.897,33.097 C33.2@51,33.2 50.975,33.225 50.975,33.875 51.758,34.658 53.449,34.658 53.863,35.073 54.632,35.073 55.016,35.457 55.444,35.457
NRSTC1MS: D7.2 R27.1 R59.1 R272.1 U1.W3 | length 123.2
  Top Layer w0.09: 56.11,38.46 57.01,38.46 U1.W3@57.375,38.825
  Top Layer w0.1: R59.1@21.48,35.245 21.475,35.24 21.475,34.625 v1@21.49,34.61 ; v2(48.805,38.061) R27.1@48.805,38.872 48.805,38.904 49.542,38.904 49.831,39.194 49.936,39.194 49.938,39.192 50.559,39.192 50.561,39.194 52.93,39.194 53.474,38.65 54.531,38.65 54.787,38.394 55.077,38.394 55.319,38.635 55.764,38.635 55.939,38.46 56.11,38.46
  Bottom Layer w0.1: R272.1@21.505,33.882 21.505,34.595 21.49,34.61 21.49,34.694 21.972,35.176 ; v2(48.805,38.061) 48.805,38.016 48.314,37.526 43.556,37.526 43.288,37.258 43.288,35.651 41.626,33.989 26.279,33.989 25.092,35.176 21.972,35.176 ; D7.2@77.88,61.563 77.88,63.32 72.735,68.465 43.114,68.465 28.049,53.4 28.049,50.003 26.618,48.572 26.618,45.92 26.431,45.733 26.431,39.267 25.501,38.337 25.133,38.337 21.972,35.176
  other v1: 21.49,34.6
OSC32_IN: C86.1 U1.AA2 X1.2 | length 6.4
  Top Layer w0.09: 55.625,37.525 56,37.525 56.05,37.575 56.625,37.575 U1.AA2@56.875,37.825
  Top Layer w0.1: X1.2@51.059,36.475 51.434,36.85 53.271,36.85 53.296,36.875 54.052,36.875 54.702,37.525 55.625,37.525
OSC32_OUT: R64.1 U1.AA1 | length 2.5
  Top Layer w0.09: 56.05,37.825 U1.AA1@56.375,37.825
  Top Layer w0.1: R64.1@53.935,37.575 54.436,37.575 54.597,37.735 55.695,37.735 55.784,37.825 56.05,37.825
PMIC_WAKEUPn: R46.1 U1.W7 | length 46.6
  Top Layer w0.09: U1.W7@59.375,38.825 59.375,38.802 59.475,38.702 v2(59.475,38.325)
  Top Layer w0.1: R46.1@31.15,50.448 31.15,50.942 35.501,55.293 39.879,55.293 41.683,53.488 41.683,53.37 44.316,50.738 44.316,47.708 46.24,45.785 46.24,42.779 44.461,41 v2(44.43,41)
  Bottom Layer w0.09: v2(44.43,41) 44.43,39.527 44.833,39.123 56.341,39.123 57.139,38.325 57.851,38.325 58.206,37.97 58.492,37.97 58.637,38.115 59.265,38.115 v2(59.475,38.325)
  other v3: 31.15,51.033
PWR_CPU_ON: R60.1 R272.2 U1.AB4 | length 40.2
  Top Layer w0.09: 55.627,36.457 56.927,36.457 57.125,36.655 57.125,36.929 57.271,37.075 57.625,37.075 U1.AB4@57.875,37.325
  Top Layer w0.095: 55.57,36.455 55.625,36.455
  Top Layer w0.1: v1(22.5,34.6) 22.514,34.614 22.514,35.229 R60.1@22.53,35.245 ; v2(55.077,36.225) 55.307,36.455 55.57,36.455
  Bottom Layer w0.1: R272.2@22.405,33.882 22.936,33.882 23.265,33.553 37.33,33.553 38.666,32.217 48.438,32.217 49.9,33.679 49.9,34.006 51.228,35.335 54.815,35.335 55.083,35.603 v2@55.083,36.219 ; R272.2@22.471,34.068 22.5,34.097 v1(22.5,34.6)
PWR_ON: R61.1 U1.AD3 | length 36.9
  Top Layer w0.09: 56.084,36.26 57.09,36.26 57.128,36.298 57.348,36.298 U1.AD3@57.375,36.325
  Top Layer w0.1: v1(23.575,34.6) 23.58,34.605 R61.1@23.58,35.245 ; v1(49.475,33.855) 50.678,35.058 53.276,35.058 53.671,35.453 54.474,35.453 54.865,35.844 55.241,35.844 55.659,36.262 56.082,36.262
  Bottom Layer w0.1: v1(23.575,34.6) 24.4,33.775 37.982,33.775 39.197,32.561 48.18,32.561 v1(49.475,33.855)
VBAT: C87.2 D6.3 U1.T6 | length 12.2
  Top Layer w0.15: v2@58.875,39.933 U1.T6@58.875,40.325
  Bottom Layer w0.3: C87.2@50.485,42.988 50.485,42.185 50.423,42.123 50.423,41.923 50.073,41.573 D6.3@49.873,41.573 50.976,40.471 53.326,40.471 53.642,40.788 55.87,40.788 56.299,40.358 58.427,40.358 v2@58.864,39.921 ; v2@58.831,39.889 v2@58.864,39.921 ; v2(58.875,39.91) v2@58.864,39.921 ; v2@58.875,39.933 v2@58.864,39.921
VDD1_DDR: C2.2 C3.2 C4.1 C5.1 C6.1 C7.1 C8.1 C40.2 U2.F1 U2.F12 U2.G4 U2.G9 U2.T4 U2.T9 U2.U1 U2.U12 U26.44 | length 153
  Top Layer w0.15: C5.1@79.559,37.48 79.584,37.48 C5.1@79.764,37.66 ; C5.1@79.765,37.66 79.765,37.68 79.979,37.894 80.659,37.894 80.859,37.694 80.888,37.723 81.088,37.723 81.415,38.05 82.641,38.05 82.936,38.345 83.277,38.345 83.28,38.348 83.628,38.348 83.945,38.032 84.577,38.032 84.698,38.153 84.893,38.153 ; 86.059,38.044 86.632,38.044 86.925,38.337 87.252,38.337 U2.G4@87.259,38.344 ; U2.T4@87.259,44.215 87.518,44.215 87.837,44.534 88.977,44.534 88.992,44.519 89.33,44.519
  Top Layer w0.2: v4(80.34,45.025) 80.421,45.025 80.56,44.886 80.839,44.886 U2.U12@80.86,44.865
  Top Layer w0.21: 24.775,46 U26.44@25.33,46
  Top Layer w0.22: U2.T9@83.26,44.215 83.275,44.2 83.415,44.2 83.625,43.99 v4(83.659,43.99) ; 84.893,38.153 85.034,38.294 85.44,38.294 ; 86.059,38.044 85.809,38.294 85.44,38.294 ; 89.33,44.519 89.655,44.844 89.659,44.844 90,44.844 90.075,44.919 90.384,44.919 91.159,45.694 C6.1@91.184,45.694 ; U2.F1@89.65,37.683 90.561,38.594 91.179,38.594 91.034,38.739 91.034,40.316 v4(90.16,41.19) ; v4@90.146,41.176 86.685,41.176 85.44,39.931 85.44,38.294 ; C7.1@91.21,38.54 91.355,38.685 C7.1@91.411,38.685 ; C7.1@91.41,38.685 91.588,38.863 92.127,38.863 C3.2@92.183,38.919
  Top Layer w0.25: v1(19.702,45.473) 19.975,45.2 21.575,45.2 21.82,45.445 21.82,45.635 21.935,45.75 C40.2@22.005,45.75 ; C40.2@22.01,45.635 22.165,45.79 22.44,45.79 22.65,46 24.775,46
  Top Layer w0.3: C6.1@91.184,45.694 C6.1@91.209,45.694 ; C6.1@91.208,45.694 91.458,45.944 C2.2@92.208,45.944
  Top Layer w0.5: v1(19.702,45.473) v1@19.702,46.196
  Signal Layer 2 w0.6: v1(19.7,46.198) 19.639,46.137 19.639,45.64 19.702,45.576 v1(19.702,45.473)
  Signal Layer 2 w0.7: v1(19.7,46.198) 18.818,47.08 18.238,47.08 16.598,45.44 15.323,45.44 14.898,45.865 14.898,52.74 21.708,59.55 66.223,59.55 76.132,49.641 88.493,49.641 90.622,47.513 90.622,46.853 90.614,46.844 90.614,46.244 90.622,46.235 90.622,45.57 90.16,45.108 v4(90.16,44.915)
  Bottom Layer w0.2: v4@80.341,45.019 v4@80.377,44.983 ; C4.1@81.593,44.983 C4.1@81.63,44.947
  Bottom Layer w0.22: C8.1@83.461,44.54 C8.1@83.481,44.54
  Bottom Layer w0.3: v4@80.377,44.983 C4.1@81.593,44.983 ; C4.1@81.63,44.947 81.734,45.052 81.788,45.052 82.721,45.985 84.006,45.985 84.018,45.985 ; C8.1@83.473,44.528 C8.1@83.485,44.54 ; C8.1@83.481,44.54 C8.1@83.485,44.54 ; v4(83.659,43.99) 83.59,44.059 83.59,44.435 C8.1@83.485,44.54 ; v4(90.16,41.19) 90.784,41.815 90.784,44.29 v4(90.16,44.915) ; v4@90.159,44.89 88.684,46.365 86.723,46.365 86.343,45.985 84.018,45.985 ; C8.1@83.485,44.54 83.59,44.645 83.694,44.645 84.018,44.969 84.018,45.985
